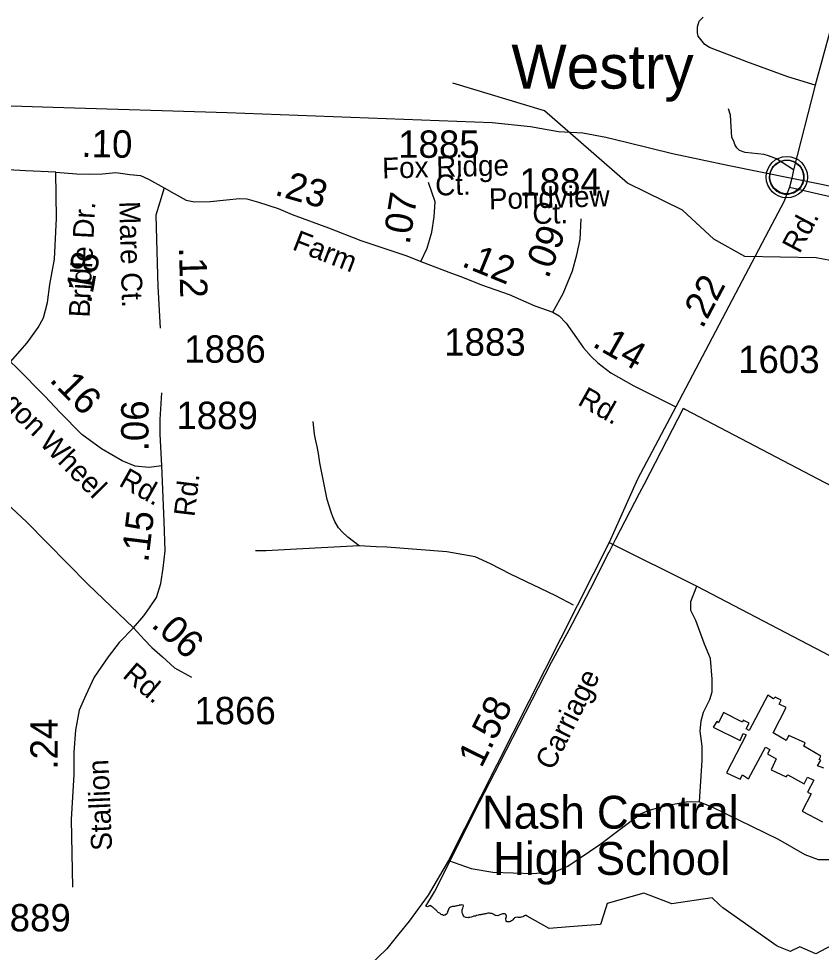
# Model space of a CAD drawing. Extents: x 2220236 to 2384410, y 720751 to 894131.
# Drawn here: x 2322567 to 2326230, y 803754 to 808018 of the extents above; entities that cross this region are included whole.
import ezdxf

# ---------------------------------------------------------------- set-up
doc = ezdxf.new("R2010")
doc.units = 0
doc.layers.add('Default', color=7, linetype='Continuous')

msp = doc.modelspace()

# ---------------------------------------------------------------- linework, layer by layer
at = {"layer": 'Default'}
msp.add_line((2325262.5, 805626.4), (2325661.6, 805425.8), dxfattribs=at)
for points in [[(2326568.2, 810272.9), (2326569.8, 810183), (2326568.1, 810143.3), (2326561.5, 810070.5), (2326543.3, 809895.2), (2326531.8, 809757.9), (2326513.6, 809552.8), (2326498.7, 809339.5), (2326493.8, 809233.6), (2326479.7, 809112.1), (2326464.8, 808978.1), (2326446.7, 808814.4), (2326408.6, 808584.5), (2326390.5, 808490.2), (2326369, 808399.3), (2326345.6, 808281.4), (2326273, 807970.7), (2326201.9, 807714.1), (2326104, 807327.2), (2326095.2, 807289.9)], [(2326201.9, 807714.1), (2326077.5, 807752.6), (2325890.8, 807820.6), (2325720.3, 807886.9), (2325698.1, 807900.6), (2325667.6, 807938.2), (2325665.5, 807954.3), (2325665.3, 807980.3), (2325673, 808006.2), (2325690.6, 808024.5)], [(2328776.1, 805064.4), (2328531, 805369.5), (2328386.1, 805685.2), (2328225.9, 805898.5), (2328117, 805979.4), (2327957.9, 806028.7), (2327373.9, 806063.9), (2327132, 806178.7), (2326619.9, 806532), (2326485, 806664.3), (2326365.9, 806895.8), (2326207, 806925.3), (2325881.9, 806931.8), (2325739.8, 807011.3), (2325596.9, 807143.3), (2325345.9, 807267.6), (2324967, 807596.7), (2324548.9, 807724.1)], [(2321488.8, 807653.4), (2322722.5, 807614.6), (2323518.4, 807589.3), (2324728.3, 807544.3), (2324902.4, 807526.2), (2325030.8, 807503.6), (2325142.6, 807496.8), (2325246.8, 807477.8), (2325341, 807454.9), (2325551.4, 807403.2), (2325809.9, 807348), (2326238.6, 807260.7), (2327130.5, 807060.4), (2328066, 806862.6), (2329318.5, 806586.2), (2329681.9, 806506.8), (2329765.5, 806488.4), (2329846, 806471), (2330182.1, 806397.6), (2331380.2, 806148.5)], [(2326104, 807327.2), (2326025.5, 807378.4), (2325989.4, 807391.9), (2325969.3, 807397.7), (2325883.3, 807406.8), (2325857.1, 807416.5), (2325845, 807428.4), (2325835, 807444.2), (2325830.8, 807458.3), (2325822.5, 807476.1), (2325815.5, 807578.1), (2325807.2, 807605.9)], [(2322736.3, 807317.9), (2322598.7, 807323.7), (2322518.4, 807327.5), (2322432.4, 807325.6), (2322222.8, 807331.7)], [(2322530.4, 806450.3), (2322606.3, 806537.8), (2322656, 806608.6), (2322680.9, 806652.5), (2322698.1, 806721.4), (2322709.5, 806803.6), (2322730.6, 806920.2), (2322740.1, 807107.6), (2322736.3, 807317.9)], [(2322736.3, 807317.9), (2322831.3, 807310.2), (2322892.5, 807308.3), (2322949.8, 807310.2), (2323011, 807315.9), (2323074, 807306.4), (2323123.7, 807302.5), (2323160, 807285.3), (2323230.7, 807245.2)], [(2324402.7, 806908.8), (2324431.3, 806970), (2324452.4, 807042.6), (2324463.8, 807113.4), (2324467.7, 807182.2), (2324437.1, 807270.2)], [(2326095.2, 807289.9), (2326085.5, 807249), (2326059.1, 807181.2), (2326004.5, 807078.6), (2325566.3, 806246.1)], [(2323230.7, 807245.2), (2323211.6, 807180.2), (2323192.5, 807120.9), (2323196.3, 807010), (2323202.1, 806795.8), (2323213.2, 806605.5)], [(2323230.7, 807245.2), (2323276.2, 807219.9), (2323331.6, 807189.3), (2323369.8, 807181.7), (2323440.6, 807183.6), (2323515.1, 807191.2), (2323574.3, 807197), (2323608.7, 807195.1), (2323662.3, 807179.8), (2323752.1, 807151.1), (2323815.2, 807124.3), (2323981.4, 807063.1), (2324128.6, 807005.8), (2324338.8, 806935), (2324402.7, 806908.8)], [(2326085.5, 807249), (2327880.4, 806836.6), (2328201.1, 806770), (2328830.1, 806646.9), (2328928.4, 806619.9), (2328946.3, 806612.2), (2328974.8, 806582.4), (2328987, 806562.7), (2328999.1, 806550.8), (2329023.4, 806518.9), (2329076, 806469.7), (2329104, 806459.8), (2329260.3, 806413.6), (2329290.6, 806402)], [(2325004.3, 806677.7), (2325052, 806763.7), (2325094.1, 806867), (2325115.1, 806939.7), (2325130.3, 807009.9), (2325134.1, 807103.6)], [(2324402.7, 806908.8), (2324541.8, 806855.5), (2324585.7, 806840.2), (2324679.4, 806802), (2324805.5, 806758), (2324922.1, 806706.4), (2325004.3, 806677.7)], [(2325004.3, 806677.7), (2325034.5, 806660.7), (2325065.1, 806628.2), (2325112.9, 806561.3), (2325145.3, 806515.4), (2325179.7, 806475.3), (2325210.3, 806446.6), (2325269.6, 806400.7), (2325374.7, 806341.4), (2325481.7, 806287.9), (2325566.3, 806246.1)], [(2323220.9, 805975.7), (2323160.5, 805968.9), (2323099.3, 805974.6), (2323040.1, 805999.5), (2322944.5, 806053), (2322854.7, 806119.9), (2322755.3, 806221.3), (2322688.4, 806292), (2322557.2, 806425.5), (2322530.4, 806450.3)], [(2323220.9, 805975.7), (2323213.2, 806120.4), (2323213.2, 806187.3), (2323220.9, 806309.7)], [(2325566.3, 806246.1), (2325392.1, 805915.1), (2325262.5, 805626.4), (2324528.6, 804173.5), (2324435.7, 804015.1), (2324349.2, 803896.6), (2324302.1, 803839.5), (2324247.6, 803770), (2324118.9, 803647.6)], [(2324484.5, 803935.2), (2324482, 803936.8), (2324477.2, 803940.9), (2324475.2, 803943.2), (2324473.5, 803944.6), (2324469.5, 803948.7), (2324467.5, 803951), (2324464.5, 803953.4), (2324462.5, 803956.4), (2324457.5, 803959.8), (2324455.8, 803961.1), (2324451.5, 803964.3), (2324449.2, 803965.2), (2324445.8, 803967.5), (2324444.8, 803967.3), (2324443.2, 803966.6), (2324441.2, 803966), (2324439, 803965.4), (2324437.5, 803964.4), (2324435.8, 803963.4), (2324432.2, 803962.7), (2324428.2, 803963.3), (2324425.5, 803964.8), (2324464.2, 804029.9), (2324516.5, 804131.9), (2324647, 804395.9), (2324762.5, 804619.9), (2324999.5, 805079.1), (2325007.2, 805093.3), (2325079, 805227.1), (2325094, 805255.6), (2325198, 805455.8), (2325258.2, 805575), (2325261.8, 805581.4), (2325293, 805642.8), (2325400.8, 805851.8), (2325422.8, 805894.3), (2325601.2, 806238.8), (2325607.8, 806235.3), (2326854, 805581.7)], [(2324484.5, 803935.2), (2324482, 803936.8), (2324477.2, 803940.9), (2324475.2, 803943.2), (2324473.5, 803944.6), (2324469.5, 803948.7), (2324467.5, 803951), (2324464.5, 803953.4), (2324462.5, 803956.4), (2324457.5, 803959.8), (2324455.8, 803961.1), (2324451.5, 803964.3), (2324449.2, 803965.2), (2324445.8, 803967.5), (2324444.8, 803967.3), (2324443.2, 803966.6), (2324441.2, 803966), (2324439, 803965.4), (2324437.5, 803964.4), (2324435.8, 803963.4), (2324432.2, 803962.7), (2324428.2, 803963.3), (2324425.5, 803964.8), (2324464.2, 804029.9), (2324516.5, 804131.9), (2324647, 804395.9), (2324762.5, 804619.9), (2324999.5, 805079.1), (2325007.2, 805093.3), (2325079, 805227.1), (2325094, 805255.6), (2325198, 805455.8), (2325258.2, 805575), (2325261.8, 805581.4), (2325293, 805642.8), (2325400.8, 805851.8), (2325422.8, 805894.3), (2325601.2, 806238.8), (2325607.8, 806235.3), (2326854, 805581.7)], [(2324121.1, 805610.8), (2324069.9, 805650.5), (2324045.1, 805673.7), (2324026.9, 805693.5), (2324010.3, 805721.6), (2324000.5, 805743.1), (2323993.9, 805764.6), (2323975.7, 805822.5), (2323954.2, 805928.4), (2323941, 805989.6), (2323936, 806032.6), (2323928.8, 806064.3), (2323922.8, 806090.4), (2323917.8, 806120.2), (2323911.2, 806178.1)], [(2323091.4, 805236.9), (2323138.7, 805291.2), (2323163.6, 805327.5), (2323196, 805375.3), (2323215.2, 805438.4), (2323226.6, 805509.2), (2323236.2, 805587.6), (2323230.4, 805721.4), (2323220.9, 805975.7)], [(2322420.2, 805889.5), (2322602.5, 805720.3), (2322884.8, 805433.5), (2323091.4, 805236.9)], [(2324121.1, 805610.8), (2323835.7, 805595.6), (2323696, 805588.1), (2323648, 805587.5)], [(2325099.6, 805339.6), (2325018.6, 805382.6), (2324812, 805481.8), (2324721.1, 805528.1), (2324650, 805561.2), (2324521.1, 805582.7), (2324247.5, 805604), (2324198.8, 805605.9), (2324121.1, 805610.8)], [(2325674.3, 804441.7), (2325685.9, 804629.6), (2325685.9, 804695.1), (2325677.4, 804764.8), (2325681.7, 804811.2), (2325692.2, 804851.4), (2325721.8, 804908.4), (2325732.3, 804944.3), (2325732.3, 805001.3), (2325724.9, 805096.3), (2325697.5, 805161.8), (2325657.4, 805269.5), (2325634.1, 805315.9), (2325634.1, 805356.1), (2325661.6, 805425.8)], [(2325661.6, 805425.8), (2326471.5, 805003.4), (2327267.6, 804591.6), (2327819.8, 804306.5), (2327956, 804230.5)], [(2323091.4, 805236.9), (2323026.4, 805170), (2322974.8, 805103.1), (2322911.7, 805011.3), (2322873.5, 804929.1), (2322842.9, 804860.2), (2322825.7, 804768.4), (2322818.1, 804669), (2322818.1, 804565.8), (2322806.7, 804360.3), (2322813.2, 804052.3)], [(2323091.4, 805236.9), (2323141.1, 805181.4), (2323175.5, 805147), (2323223.2, 805103.1), (2323278.7, 805053.3), (2323355.1, 805011.3)], [(2326241.3, 804594.8), (2326212.8, 804605.3), (2326228.6, 804631.7), (2326221.2, 804634.9), (2326228.6, 804649.7), (2326150.5, 804696.1), (2326156.8, 804710.9), (2326081.8, 804744.7), (2326069.2, 804721.5), (2326011.1, 804756.3), (2326070.7, 804872.5), (2326038, 804887.3), (2326047.5, 804905.2), (2326019, 804918.9), (2326012.7, 804911.5), (2325986.3, 804928.4), (2325901.8, 804767.9), (2325887, 804774.3), (2325901.8, 804800.7), (2325873.3, 804814.4), (2325871.2, 804806), (2325784.6, 804850.3), (2325761.4, 804802.8), (2325752.9, 804808.1), (2325737.1, 804782.7), (2325859.6, 804721.5), (2325874.4, 804754.2), (2325888.1, 804747.9), (2325798.3, 804573.7), (2325859.6, 804545.1), (2325871.2, 804564.2), (2325897.6, 804547.3), (2325975.7, 804691.9), (2325995.8, 804680.3), (2325984.2, 804660.2), (2326024.3, 804638.1), (2326002.1, 804588.4), (2326070.7, 804555.7), (2326077.1, 804564.2), (2326152.1, 804524), (2326166.8, 804553.6), (2326196.4, 804540.9), (2326167.9, 804486), (2326184.8, 804477.6), (2326143.6, 804399.4), (2326236.5, 804350.9)], [(2324528.6, 804173.5), (2324632.1, 804137.6), (2324731.4, 804120.7), (2324917.2, 804114.3), (2325020.7, 804124.9), (2325073.5, 804148.1), (2325219.2, 804247.4), (2325405, 804386.8), (2325445.1, 804403.7), (2325531.7, 804426.9), (2325620.4, 804443.8), (2325674.3, 804441.7)], [(2325674.3, 804441.7), (2325731.3, 804418.4), (2326033.3, 804270.6), (2326155.7, 804200.9), (2326215.9, 804177.7), (2326289.8, 804177.7), (2326448.2, 804207.3)], [(2326302.8, 803799.6), (2326205, 803748.1), (2326132.8, 803779.4), (2326091.2, 803758.9), (2326089.5, 803758), (2326029, 803782), (2325780.2, 803957.6), (2325767.8, 803969.4), (2325731.5, 804003.6), (2325548.8, 803975.8), (2325457, 804010.6), (2325419.8, 804024.7), (2325253.2, 803976.6), (2325247, 803957), (2325222.8, 803881.8), (2325160.5, 803876.8), (2325081, 803870.4), (2324988.8, 803863.1), (2324887.5, 803918.8), (2324883.5, 803921.8), (2324879.2, 803922), (2324876, 803920.9), (2324871.5, 803918.6), (2324867.5, 803916.9), (2324862.5, 803915.1), (2324859.5, 803914.3), (2324855.5, 803912.6), (2324846.8, 803913.4), (2324841.5, 803914.9), (2324834, 803913.8), (2324830.5, 803911.4), (2324828.5, 803908.6), (2324825.5, 803906.6), (2324822, 803902.9), (2324820, 803899.6), (2324817, 803897.4), (2324811.5, 803895.5), (2324807.8, 803894.2), (2324803.5, 803893.3), (2324799, 803892.8), (2324794.5, 803894), (2324792, 803897.5), (2324791.5, 803900), (2324790.5, 803905.6), (2324791, 803909.4), (2324792.5, 803913.4), (2324793, 803918.2), (2324793, 803922.2), (2324792.2, 803923.2), (2324791, 803924.8), (2324790.5, 803926.5), (2324788.2, 803928.3), (2324785.5, 803930.4), (2324782.2, 803930.6), (2324777, 803930.7), (2324775.8, 803930.5), (2324772.2, 803929.2), (2324767, 803927.1), (2324762.8, 803925.1), (2324757.2, 803922.1), (2324753.2, 803921.1), (2324746.8, 803921.9), (2324743.5, 803922.6), (2324739.8, 803924.2), (2324737.5, 803926.1), (2324733.2, 803928.7), (2324730.5, 803929.4), (2324726.5, 803931.1), (2324724.8, 803931.8), (2324719.8, 803931.9), (2324716.2, 803932.6), (2324708, 803932.6), (2324703.8, 803932.3), (2324699, 803930.8), (2324694.8, 803929.7), (2324691.2, 803929), (2324687.5, 803928.4), (2324682.8, 803927.3), (2324678.2, 803926.8), (2324676, 803925.9), (2324669.5, 803924.9), (2324665.2, 803923.8), (2324664, 803923.4), (2324658.2, 803922), (2324656, 803921.8), (2324651.5, 803920.1), (2324644, 803919.1), (2324636.8, 803916.2), (2324632, 803914.9), (2324625.8, 803913.1), (2324620.8, 803912.9), (2324618.8, 803912.3), (2324611, 803913.9), (2324607.2, 803914.1), (2324600.5, 803917), (2324598.5, 803920.1), (2324595.2, 803924.2), (2324594.2, 803929), (2324592.8, 803931.4), (2324591.5, 803935.2), (2324590.8, 803938.6), (2324591, 803942.6), (2324591.8, 803947.9), (2324592.8, 803952.2), (2324593.5, 803955.6), (2324596, 803961.3), (2324597.2, 803965.3), (2324597, 803966.4), (2324595, 803969.4), (2324588.2, 803970.7), (2324585, 803970.2), (2324578.2, 803969), (2324576.5, 803968.8), (2324570.2, 803966.4), (2324566.5, 803965.9), (2324562.8, 803965.3), (2324560.5, 803964.5), (2324555.8, 803964.3), (2324549.8, 803962.9), (2324546.8, 803963.1), (2324542.5, 803961.8), (2324538.2, 803961), (2324533.5, 803958.2), (2324530.8, 803954.9), (2324528.8, 803950.6), (2324526.8, 803945.4), (2324524.8, 803940.9), (2324523.8, 803936.9), (2324522, 803933.4), (2324520.5, 803930.4), (2324515.5, 803925.9), (2324514, 803924.5), (2324509, 803923.5), (2324505.8, 803923.1), (2324503, 803925.1), (2324498.2, 803926.1), (2324496, 803927.7), (2324493.2, 803929.2), (2324489, 803932.6), (2324484.5, 803935.2)], [(2326302.8, 803799.6), (2326205, 803748.1), (2326132.8, 803779.4), (2326091.2, 803758.9), (2326089.5, 803758), (2326029, 803782), (2325780.2, 803957.6), (2325767.8, 803969.4), (2325731.5, 804003.6), (2325548.8, 803975.8), (2325457, 804010.6), (2325419.8, 804024.7), (2325253.2, 803976.6), (2325247, 803957), (2325222.8, 803881.8), (2325160.5, 803876.8), (2325081, 803870.4), (2324988.8, 803863.1), (2324887.5, 803918.8), (2324883.5, 803921.8), (2324879.2, 803922), (2324876, 803920.9), (2324871.5, 803918.6), (2324867.5, 803916.9), (2324862.5, 803915.1), (2324859.5, 803914.3), (2324855.5, 803912.6), (2324846.8, 803913.4), (2324841.5, 803914.9), (2324834, 803913.8), (2324830.5, 803911.4), (2324828.5, 803908.6), (2324825.5, 803906.6), (2324822, 803902.9), (2324820, 803899.6), (2324817, 803897.4), (2324811.5, 803895.5), (2324807.8, 803894.2), (2324803.5, 803893.3), (2324799, 803892.8), (2324794.5, 803894), (2324792, 803897.5), (2324791.5, 803900), (2324790.5, 803905.6), (2324791, 803909.4), (2324792.5, 803913.4), (2324793, 803918.2), (2324793, 803922.2), (2324792.2, 803923.2), (2324791, 803924.8), (2324790.5, 803926.5), (2324788.2, 803928.3), (2324785.5, 803930.4), (2324782.2, 803930.6), (2324777, 803930.7), (2324775.8, 803930.5), (2324772.2, 803929.2), (2324767, 803927.1), (2324762.8, 803925.1), (2324757.2, 803922.1), (2324753.2, 803921.1), (2324746.8, 803921.9), (2324743.5, 803922.6), (2324739.8, 803924.2), (2324737.5, 803926.1), (2324733.2, 803928.7), (2324730.5, 803929.4), (2324726.5, 803931.1), (2324724.8, 803931.8), (2324719.8, 803931.9), (2324716.2, 803932.6), (2324708, 803932.6), (2324703.8, 803932.3), (2324699, 803930.8), (2324694.8, 803929.7), (2324691.2, 803929), (2324687.5, 803928.4), (2324682.8, 803927.3), (2324678.2, 803926.8), (2324676, 803925.9), (2324669.5, 803924.9), (2324665.2, 803923.8), (2324664, 803923.4), (2324658.2, 803922), (2324656, 803921.8), (2324651.5, 803920.1), (2324644, 803919.1), (2324636.8, 803916.2), (2324632, 803914.9), (2324625.8, 803913.1), (2324620.8, 803912.9), (2324618.8, 803912.3), (2324611, 803913.9), (2324607.2, 803914.1), (2324600.5, 803917), (2324598.5, 803920.1), (2324595.2, 803924.2), (2324594.2, 803929), (2324592.8, 803931.4), (2324591.5, 803935.2), (2324590.8, 803938.6), (2324591, 803942.6), (2324591.8, 803947.9), (2324592.8, 803952.2), (2324593.5, 803955.6), (2324596, 803961.3), (2324597.2, 803965.3), (2324597, 803966.4), (2324595, 803969.4), (2324588.2, 803970.7), (2324585, 803970.2), (2324578.2, 803969), (2324576.5, 803968.8), (2324570.2, 803966.4), (2324566.5, 803965.9), (2324562.8, 803965.3), (2324560.5, 803964.5), (2324555.8, 803964.3), (2324549.8, 803962.9), (2324546.8, 803963.1), (2324542.5, 803961.8), (2324538.2, 803961), (2324533.5, 803958.2), (2324530.8, 803954.9), (2324528.8, 803950.6), (2324526.8, 803945.4), (2324524.8, 803940.9), (2324523.8, 803936.9), (2324522, 803933.4), (2324520.5, 803930.4), (2324515.5, 803925.9), (2324514, 803924.5), (2324509, 803923.5), (2324505.8, 803923.1), (2324503, 803925.1), (2324498.2, 803926.1), (2324496, 803927.7), (2324493.2, 803929.2), (2324489, 803932.6), (2324484.5, 803935.2)]]:
    msp.add_lwpolyline(points, dxfattribs=at)
msp.add_lwpolyline([(2325995.2, 807307.1), (2325996.2, 807312.7), (2325998, 807319.3), (2326000.9, 807326.5), (2326003.9, 807332.2), (2326007.2, 807337.9), (2326011, 807343.1), (2326014.9, 807347.4), (2326019.5, 807352), (2326025, 807356.6), (2326030.5, 807360.3), (2326035.3, 807363.1), (2326040.4, 807365.6), (2326045.9, 807367.9), (2326051.5, 807369.7), (2326055.8, 807370.9), (2326060.7, 807371.6), (2326064.8, 807372.3), (2326071.2, 807372.6), (2326075.6, 807372.5), (2326081.3, 807372.2), (2326086.2, 807371.5), (2326091.1, 807370.5), (2326096.1, 807369.1), (2326101.2, 807367.2), (2326107.9, 807364.2), (2326114.2, 807360.7), (2326119.2, 807357.2), (2326124.4, 807353.2), (2326127.7, 807350), (2326131.8, 807345.7), (2326135.7, 807341), (2326138.8, 807336.4), (2326141.9, 807331.4), (2326144.3, 807326.2), (2326146.4, 807321.2), (2326147.9, 807316.2), (2326149.2, 807311.6), (2326150.3, 807305.5), (2326150.9, 807300.8), (2326151.2, 807294.8), (2326151, 807289.1), (2326150.5, 807283.4), (2326149.5, 807277.9), (2326147.9, 807271.7), (2326146, 807265.9), (2326143.7, 807260.8), (2326140.5, 807254.8), (2326137.2, 807249.5), (2326133.8, 807244.8), (2326129.6, 807240.1), (2326124.3, 807235.1), (2326119.3, 807231), (2326114.3, 807227.5), (2326109.9, 807225), (2326103.1, 807221.8), (2326096, 807219.1), (2326090, 807217.6), (2326083.4, 807216.3), (2326079, 807215.8), (2326074.5, 807215.6), (2326068.9, 807215.6), (2326064.6, 807216), (2326059, 807216.7), (2326053.1, 807218), (2326048.5, 807219.3), (2326043.3, 807221.2), (2326038.7, 807223.2), (2326034.8, 807225.4), (2326028, 807229.5), (2326022.4, 807233.8), (2326017.5, 807238.3), (2326013.1, 807243.1), (2326009.9, 807247.1), (2326006.9, 807251.3), (2326002.8, 807258.4), (2326001.1, 807261.9), (2325999.4, 807265.9), (2325996.8, 807274.1), (2325995.2, 807281.2), (2325994.6, 807286.3), (2325994.2, 807292.7), (2325994.2, 807297.3), (2325994.7, 807303.8)], close=True, dxfattribs=at)
for centre, radius in [((2326072.9, 807294.7), 94.3), ((2326072.6, 807295), 76.7)]:
    msp.add_circle(centre, radius, dxfattribs=at)

# ---------------------------------------------------------------- texts
for s, height, p in [('Westry', 200, (2324815.9, 807698.9)), ('1885', 125, (2324299.1, 807382.8)), ('1884', 125, (2324852.3, 807210.2)), ('1883', 125, (2324509.2, 806479)), ('1886', 125, (2323323, 806447)), ('1603', 125, (2325850.6, 806399.7)), ('1889', 125, (2323287, 806144)), ('1866', 125, (2323368.7, 804795.9)), ('Nash Central', 150, (2324682.2, 804319.1)), ('High School', 150, (2324732.7, 804108)), ('1889', 125, (2322433.1, 803849.7))]:
    msp.add_text(s, height=height, dxfattribs=at).set_placement(p)
for s, height, rotation, p in [('.10', 125, 359.0091, (2322852.9, 807386.5)), ('Fox Ridge', 95, 1.4273, (2324227, 807288)), ('.23', 125, 344.0482, (2323730.8, 807214.7)), ('Ct.', 95, 1.4273, (2324469.1, 807210.4)), ('Pondview', 95, 1.4273, (2324714.4, 807147.5)), ('.07', 125, 80.7929, (2324350.7, 806983.5)), ('Mare Ct.', 95, 271.5336, (2323026, 807183.8)), ('Ct.', 95, 1.4273, (2324912.8, 807080.1)), ('Bridle Dr.', 95, 87.0805, (2322890.2, 806652.1)), ('Rd.', 95, 62.1596, (2326130.6, 806941.6)), ('Farm', 95, 338.7051, (2323810.9, 806965.8)), ('.09', 125, 69.4732, (2324983.8, 806826.9)), ('.12', 125, 271.5336, (2323298.5, 806973.6)), ('.12', 125, 337.7879, (2324583.7, 806889.8)), ('.18', 125, 79.7821, (2322896.7, 806713.1)), ('.22', 125, 62.2414, (2325687.8, 806598.5)), ('.14', 125, 330.5821, (2325180.3, 806523.8)), ('Wagon', 95, 315.7314, (2322350.3, 806385.8)), ('.16', 125, 314.4416, (2322703.6, 806365.6)), ('Rd.', 95, 330.5821, (2325113.5, 806258)), ('.06', 125, 90, (2323159.6, 806042.5)), ('Wheel', 95, 314.506, (2322657.2, 806077.3)), ('Rd.', 95, 330.7403, (2323019.4, 805887.6)), ('Rd.', 95, 83.0498, (2323369.1, 805740.7)), ('.15', 125, 83.0499, (2323157.9, 805532.5)), ('.06', 125, 317.3735, (2323167.6, 805245.1)), ('Rd.', 95, 319.6443, (2323036.4, 805013.3)), ('Carriage', 95, 63.5, (2325005.2, 804580.8)), ('1.58', 125, 63.5, (2324678.8, 804592.1)), ('.24', 125, 90, (2322745.4, 804588.9)), ('Stallion', 95, 92.373, (2322993.5, 804220.3))]:
    msp.add_text(s, height=height, rotation=rotation, dxfattribs=at).set_placement(p)

doc.saveas('drawing.dxf')
